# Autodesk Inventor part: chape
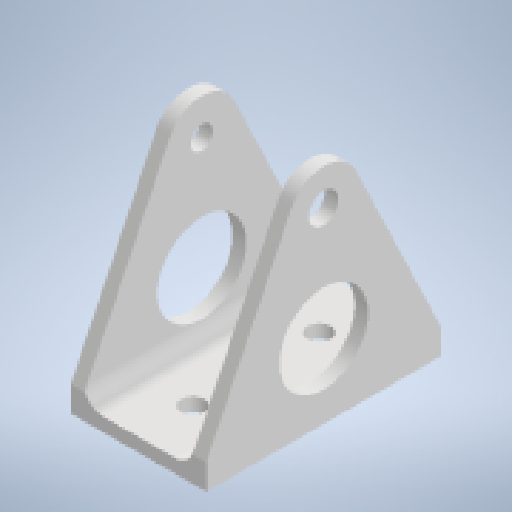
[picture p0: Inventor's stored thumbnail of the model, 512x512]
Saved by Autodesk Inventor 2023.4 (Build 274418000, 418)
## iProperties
Created: 2025-03
Part Number: chape
Material: Générique
Document SubType Name: Modeling
Designer: bruno
Density: 1 g/cm^3
Appearance: Par défaut
Author: bruno
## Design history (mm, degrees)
sketch "Esquisse1"
  geometry: L1 (0, 0)-(0, -130); L2 (0, 0)-(300, 0); L3 (300, 0)-(27.98, -130); L4 (27.98, -130)-(0, -130)
  constraints: 8 end point, 1 horizontal, 1 parallel, 1 vertical
  dimensions: "d0" = 130 distance of L1.start L1.end; "d1" = 300 distance of L1.start L2.end
extrude "Extrusion1" new body sketch "Esquisse1" distance "d2" = 150; taper "d3" = 0 deg
mirror "Symétrie1"
fillet "Congé1" dims "d7" = 40
sketch "Esquisse2"
  geometry: C1 r 49.06 at (0, 82.003); C2 r 13 at (0, 207.234); A1 r 40 centre (0, 207.234) between (36.09, 224.482) and (-36.09, 224.482) reference; 1 further point
  constraints: 2 centre point, 1 coincident
  dimensions: "d4" = 26 diameter of C2
extrude "Extrusion2" cut sketch "Esquisse2" distance "d5" = 150; taper "d6" = 0 deg
sketch "Esquisse3"
  geometry: L1 (150, 27.98)-(150, 224.482) reference; L2 (0, 27.98)-(0, 224.482) reference; L3 (15, 273.228)-(135, 273.228); L4 (135, 273.228)-(135, 15); L5 (135, 15)-(15, 15); L6 (15, 15)-(15, 273.228); L7 (0, 0)-(150, 0) reference
  constraints: 8 end point, 2 parallel, 1 horizontal, 1 perpendicular
  dimensions: "d8" = 15 distance between parallel lines of L2 L6; "d9" = 15 distance between parallel lines of L1 L4; "d10" = 15 distance between parallel lines of L5 L7
extrude "Extrusion3" cut sketch "Esquisse3" distance "d11" = 300; taper "d12" = 0 deg
fillet "Congé2" dims "d13" = 20
sketch "Esquisse4"
  geometry: L1 (0, 260)-(150, 260) reference; L2 (0, 0)-(150, 0) reference; C1 r 12.5 at (75, 200); C2 r 12.5 at (75, 60); 1 further point
  constraints: 2 centre point
  dimensions: "d14" = 25 diameter of C1; "d15" = 60 distance from line of C1.centre L1; "d16" = 25 diameter of C2; "d17" = 60 distance from line of L2 C2.centre
extrude "Extrusion4" cut sketch "Esquisse4" distance "d18" = 200; taper "d19" = 0 deg
sketch "Esquisse5"
  geometry: C1 r 13 at (0, 207.234) reference; C2 r 16.5 at (0, 207.234); 1 further point
  constraints: 1 centre point, 1 coincident
  dimensions: "d20" = 33 diameter of C2
extrude "Extrusion5" cut sketch "Esquisse5" distance "d21" = 20; taper "d22" = 0 deg
node "Solide1"
